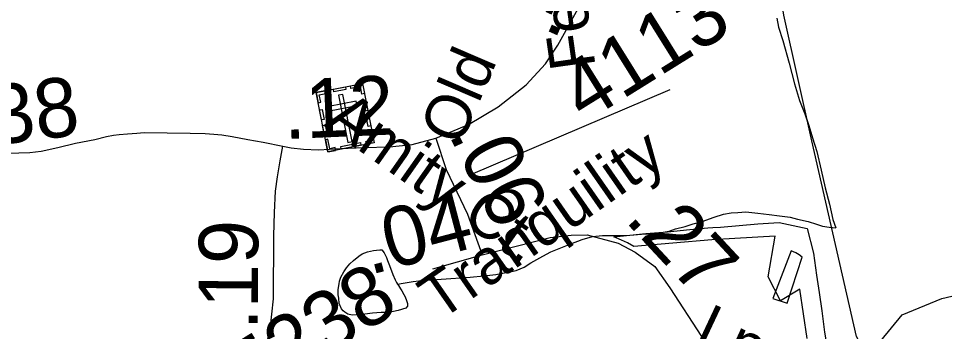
# Model space of a CAD drawing. Extents: x 2001466 to 31450019, y -30647475 to 847247.
# Drawn here: x 2152625 to 2156522, y 734514 to 735833 of the extents above; entities that cross this region are included whole.
import ezdxf

# ---------------------------------------------------------------- set-up
doc = ezdxf.new("R2010")
doc.units = 0
for name, color, linetype in [('Exist Boundary Political City Limit New', 7, 'Continuous'), ('Exist Cultural Cemetery CELL', 7, 'Continuous'), ('Exist Hydrographic Creek Single Shore', 7, 'Continuous'), ('Exist Hydrographic Misc Water Feature', 7, 'Continuous'), ('Exist Road Secondary Mileage Hundredths English Label', 7, 'Continuous'), ('Exist Road Secondary Type 51 Attributed', 7, 'Continuous'), ('Exist Road Secondary Type 51 Label', 7, 'Continuous'), ('Exist Road Secondary Type 51 Number Label', 7, 'Continuous'), ('Map Preparation Boundary City Limit Buffer Line', 7, 'Continuous')]:
    doc.layers.add(name, color=color, linetype=linetype)

msp = doc.modelspace()

# ---------------------------------------------------------------- linework, layer by layer
at = {"layer": 'Exist Boundary Political City Limit New'}
for points in [[(2155944, 734485.1), (2155912.5, 734692.7), (2155831.2, 734643.6), (2155779.8, 734744.3), (2155809.2, 734915.4), (2155639.5, 734905.6), (2155543.2, 734900.2), (2155214.2, 734872.2), (2155188.5, 734888.1), (2155162.5, 734899.7), (2155130.5, 734913.4), (2155265.5, 734926.7), (2155356.2, 734934.5), (2155450, 734943.7), (2155525.2, 734950.5), (2155547, 734951.9), (2155579.5, 734953.9), (2155737, 734967.3), (2155826.2, 734973.7), (2155944.2, 734948.5)], [(2155944.2, 734948.5), (2155970.8, 734844.2), (2155983.2, 734752.2), (2155994.5, 734678.8), (2156005.8, 734601.8), (2156017.2, 734511.8), (2156030, 734437.7), (2156034.2, 734406.9), (2156056, 734228.1), (2156062.2, 734177.6), (2156072.2, 734160.3), (2156231.8, 733848.1), (2156266.5, 733747.5), (2156323.8, 733618.4), (2156363.5, 733526.6), (2156405, 733432), (2156446, 733340.3), (2156522.2, 733162.5)]]:
    msp.add_lwpolyline(points, dxfattribs=at)
at = {"layer": 'Exist Cultural Cemetery CELL'}
for points in [[(2153877.2, 735520.8), (2154072.5, 735559.4), (2154121.9, 735309.7), (2153926.6, 735271)], [(2154081, 735516.9), (2154069.8, 735514.7), (2154063.6, 735546.3), (2154023.8, 735538.4), (2154021.6, 735549.3), (2154072.6, 735559.4)], [(2153885.6, 735478.3), (2153896.7, 735480.5), (2153890.5, 735512.1), (2153930.3, 735520), (2153928.1, 735530.9), (2153877.2, 735520.8)], [(2153949.8, 735535.2), (2154000.7, 735545.2), (2154002.9, 735534.1), (2153952, 735524)], [(2153930.4, 735462), (2153934, 735443.7), (2154049.5, 735466.5), (2154045.9, 735484.8)], [(2153989.8, 735513.2), (2153971.5, 735509.6), (2154010.8, 735310.7), (2154029.1, 735314.3)], [(2154083.9, 735443), (2154075.5, 735485.5), (2154086.7, 735487.7), (2154095.1, 735445.2)], [(2153899.9, 735405.6), (2153891.5, 735448.1), (2153902.7, 735450.3), (2153911.1, 735407.8)], [(2154096.7, 735378.3), (2154088.3, 735420.8), (2154099.5, 735423), (2154107.9, 735380.5)], [(2153913, 735339.7), (2153904.6, 735382.1), (2153915.7, 735384.4), (2153924.1, 735341.9)], [(2154089.4, 735303.2), (2154087.1, 735314.5), (2154108.7, 735318.8), (2154100.9, 735358.4), (2154111.8, 735360.6), (2154121.9, 735309.7)], [(2153959, 735277.5), (2153956.8, 735288.8), (2153935.2, 735284.5), (2153927.3, 735324.2), (2153916.4, 735322), (2153926.5, 735271.1)], [(2153980.7, 735293.4), (2154063.9, 735309.9), (2154066.1, 735298.7), (2153982.9, 735282.3)]]:
    msp.add_lwpolyline(points, close=True, dxfattribs=at)
at = {"layer": 'Exist Hydrographic Creek Single Shore'}
for points in [[(2156178.2, 734443.1), (2156152.2, 734492.9), (2155964.2, 735316.9), (2155845.2, 735847.4), (2155810.2, 736064.7)], [(2156178.2, 734443.1), (2156253.3, 734474.4), (2156344.1, 734584.1), (2156510.2, 734652.9), (2156984.3, 734764.6), (2157849.2, 735025.8), (2157924.3, 735128.7)]]:
    msp.add_lwpolyline(points, dxfattribs=at)
at = {"layer": 'Exist Hydrographic Misc Water Feature'}
for points in [[(2155816.9, 735834.7), (2155823.5, 735796.8), (2155841.7, 735740.9), (2155868.4, 735645.3), (2155890.7, 735557.5), (2155911.2, 735487.4), (2155933.6, 735431.8), (2155951.6, 735382), (2155965.8, 735329.9), (2155984.2, 735272), (2156002.7, 735194.1), (2156019.3, 735120.2), (2156037.6, 735050.6), (2156051.9, 734986.3), (2156064.2, 734950.4)], [(2154219.8, 734714.2), (2154244, 734718.2), (2154286.2, 734724.4), (2154334, 734730.6), (2154384, 734733.1), (2154443.9, 734737.4), (2154525.7, 734743.8), (2154583.7, 734748.4), (2154633.8, 734754.6), (2154699.6, 734767), (2154719.3, 734770.9), (2154753.5, 734785.2), (2154781.2, 734803.3), (2154831.4, 734831.4), (2154865.1, 734849.8), (2154948.9, 734884.2), (2154996.7, 734902.5), (2155040.8, 734914.9), (2155082.6, 734919.1), (2155136.8, 734919.1), (2155182.7, 734919.4), (2155246.3, 734924), (2155296.3, 734926.1), (2155362.7, 734936.4), (2155390.4, 734946.8), (2155430.4, 734957), (2155464.2, 734967.3), (2155502.2, 734977.4), (2155552, 734995.8), (2155592.2, 735008), (2155623.8, 735014.2), (2155652.3, 735016.3), (2155685.7, 735018.6), (2155735.7, 735012.6), (2155783.7, 735007), (2155827.8, 735001.1), (2155871.9, 734995.3), (2155903.7, 734987.6), (2155948, 734977.7), (2155983.8, 734966.2), (2156008, 734958.4), (2156036.3, 734954.2), (2156064.2, 734950.4)], [(2154219.8, 734714.2), (2154223.9, 734708.3), (2154232.3, 734694), (2154238.2, 734686.2), (2154246.2, 734670.4), (2154252.2, 734660.2), (2154258.3, 734644.3), (2154262.2, 734632.3), (2154262.4, 734628.2), (2154262.4, 734620.5), (2154254.8, 734612.4), (2154222.4, 734602.2), (2154182.9, 734594), (2154150.5, 734593.7), (2154115, 734591.7), (2154082.8, 734587.2), (2154062.9, 734585.4), (2154028.9, 734582.8), (2154010.8, 734587.1), (2153998.5, 734595.1), (2153990.5, 734600.8), (2153984.8, 734609), (2153974.7, 734632.8), (2153972.3, 734654.7), (2153970.4, 734668.7), (2153970.2, 734690.6), (2153974.3, 734714.8), (2153976, 734726.7), (2153981.9, 734742.8), (2153993.8, 734765), (2154005.7, 734783.1), (2154019.8, 734798.8), (2154035.2, 734813.1), (2154057.4, 734831.2), (2154071.5, 734841.3), (2154093.3, 734849.3), (2154119.3, 734855.5), (2154131, 734857.4), (2154145.1, 734857.7), (2154153.3, 734857.7), (2154163.2, 734845.7), (2154173.4, 734825.8), (2154177.3, 734813.9), (2154185.7, 734791.9), (2154199.7, 734754.1), (2154210.1, 734731.9), (2154216.1, 734720), (2154219.8, 734714.2)], [(2155876.8, 734853.4), (2155800.1, 734653.3), (2155860, 734633.6), (2155922.9, 734827.7), (2155910.6, 734837.7), (2155896.7, 734845.5), (2155876.8, 734853.4)]]:
    msp.add_lwpolyline(points, dxfattribs=at)
at = {"layer": 'Exist Road Secondary Type 51 Attributed'}
for points in [[(2154380.9, 735329.4), (2154518, 735387), (2154644.1, 735460.3), (2154761.3, 735553.5), (2154842.9, 735642.5), (2154895.2, 735720), (2155007.7, 735927.3), (2155132.7, 736201.7), (2155268.8, 736534.7), (2155344.1, 736753.5), (2155418.9, 737020.5), (2155482.7, 737258.2), (2155510.5, 737303.3)], [(2152565, 735265.2), (2152626.1, 735266.7), (2152672.6, 735268.1), (2152720.5, 735273.9), (2152790.3, 735289.9), (2152865.2, 735307.5), (2152945.8, 735323.6), (2152994.5, 735336.1), (2153025, 735340.9), (2153048.9, 735344.7), (2153084.2, 735346.6), (2153123.3, 735350.4), (2153153.9, 735352.3), (2153346.9, 735350.3), (2153410.8, 735348.2), (2153447.5, 735346), (2153481.1, 735342.8), (2153524.4, 735336.3), (2153590.4, 735323.3), (2153654.2, 735311.4), (2153737.7, 735294.5)], [(2153737.7, 735294.5), (2153772.8, 735288.5), (2153824, 735282.5), (2153887, 735279.7), (2153979.6, 735285.5), (2154078, 735289.6), (2154186.8, 735291.7), (2154282, 735302.2), (2154380.9, 735329.4)], [(2154380.9, 735329.4), (2154424.3, 735196.5), (2154514.3, 735009), (2154575.9, 734836.9)], [(2153605.8, 734332.2), (2153628.5, 734361.9), (2153664.1, 734441.5), (2153684.5, 734522.1), (2153698.1, 734651.9), (2153699.7, 734916.9), (2153701.8, 735015.3), (2153706.1, 735104.9), (2153715.2, 735165.2), (2153726.2, 735233.6), (2153737.7, 735294.5)], [(2154575.9, 734836.9), (2154862.1, 734910), (2154951, 734919.9), (2155018.1, 734921.9), (2155148.4, 734886.3), (2155219.5, 734848.8), (2155302.4, 734787.6), (2155365.5, 734698.7), (2155499.8, 734493.3), (2155622.2, 734311.6), (2155655.7, 734241.8)], [(2154368.6, 734777.7), (2154575.9, 734836.9)]]:
    msp.add_lwpolyline(points, dxfattribs=at)
at = {"layer": 'Exist Road Secondary Type 51 Number Label'}
msp.add_line((2154527.8, 735176.3), (2155367.2, 735533.6), dxfattribs=at)
at = {"layer": 'Map Preparation Boundary City Limit Buffer Line'}
for points in [[(2155944, 734485.1), (2155912.5, 734692.7), (2155831.2, 734643.6), (2155779.8, 734744.3), (2155809.2, 734915.4), (2155639.5, 734905.6), (2155543.2, 734900.2), (2155214.2, 734872.2), (2155188.5, 734888.1), (2155162.5, 734899.7), (2155130.5, 734913.4), (2155265.5, 734926.7), (2155356.2, 734934.5), (2155450, 734943.7), (2155525.2, 734950.5), (2155547, 734951.9), (2155579.5, 734953.9), (2155737, 734967.3), (2155826.2, 734973.7), (2155944.2, 734948.5)], [(2155944.2, 734948.5), (2155970.8, 734844.2), (2155983.2, 734752.2), (2155994.5, 734678.8), (2156005.8, 734601.8), (2156017.2, 734511.8), (2156030, 734437.7), (2156034.2, 734406.9), (2156056, 734228.1), (2156062.2, 734177.6), (2156072.2, 734160.3), (2156231.8, 733848.1), (2156266.5, 733747.5), (2156323.8, 733618.4), (2156363.5, 733526.6), (2156405, 733432), (2156446, 733340.3), (2156522.2, 733162.5)]]:
    msp.add_lwpolyline(points, dxfattribs=at)

# ---------------------------------------------------------------- texts
at = {"layer": 'Exist Road Secondary Mileage Hundredths English Label'}
for s, rotation, p in [('.45', 66.0653, (2154879.4, 735734.5)), ('.12', 2.4381, (2153743.5, 735324.7)), ('.38', 6.906, (2152428.5, 735288.1)), ('.06', 296.3888, (2154432.7, 735347.9)), ('.04', 14.7301, (2154102.2, 734752)), ('.27', 312.8722, (2155172.5, 734982.6)), ('.19', 89.6605, (2153631.5, 734518.8))]:
    msp.add_text(s, height=250, rotation=rotation, dxfattribs=at).set_placement(p)
at = {"layer": 'Exist Road Secondary Type 51 Label'}
for s, rotation, p in [('New Faison St.', 36.5362, (2151529.5, 735415.8)), ('Ferrell', 97.9833, (2155054, 735630.4)), ('Old', 66.7167, (2154483.5, 735290.7)), ('Amity Ct.', 324.949, (2153906.1, 735382.6)), ('Tranquility', 34.8522, (2154397.8, 734556.1)), ('Ln', 334.8654, (2155460.4, 734462.9))]:
    msp.add_text(s, height=190, rotation=rotation, dxfattribs=at).set_placement(p)
at = {"layer": 'Exist Road Secondary Type 51 Number Label'}
for s, p in [('4113', (2155006.6, 735391.5)), ('5238', (2153603.4, 734212.6))]:
    msp.add_text(s, height=250, rotation=31.918, dxfattribs=at).set_placement(p)

doc.saveas('drawing.dxf')
